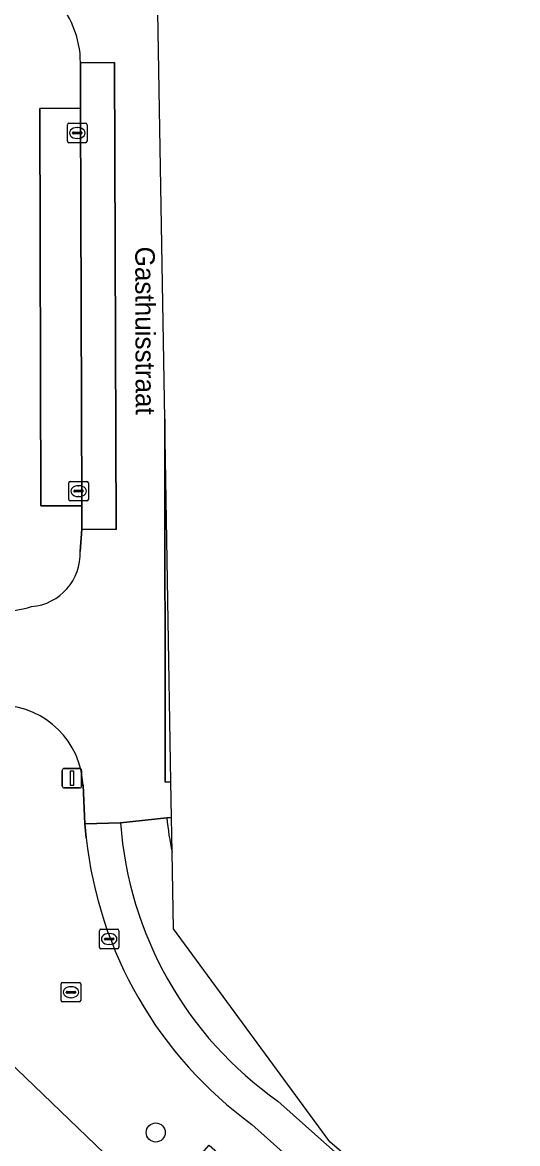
# Model space of a CAD drawing. Extents: x 161881 to 162523, y 381678 to 382381.
# Drawn here: x 162085.9 to 162111.3, y 382190.1 to 382247.6 of the extents above; entities that cross this region are included whole.
import ezdxf

# ---------------------------------------------------------------- set-up
doc = ezdxf.new("R2010")
doc.units = 0
for name, color, linetype in [('IMGEO_Boom', 7, 'Continuous'), ('IMGEO_Brandkraan', 7, 'Continuous'), ('IMGEO_Kolk', 7, 'Continuous'), ('IMGEO_Lichtmast', 7, 'Continuous'), ('IMGEO_Openbare_ruimte_label', 7, 'Continuous'), ('IMGEO_Pand', 7, 'Continuous'), ('IMGEO_Parkeervlak_open', 7, 'Continuous'), ('IMGEO_Rijbaan_lokaal_gesloten', 7, 'Continuous'), ('IMGEO_Rijbaan_lokaal_open', 7, 'Continuous'), ('IMGEO_Voetpad_open', 7, 'Continuous')]:
    doc.layers.add(name, color=color, linetype=linetype)

msp = doc.modelspace()

# ---------------------------------------------------------------- linework, layer by layer
at = {"layer": 'IMGEO_Boom'}
msp.add_circle((162092.765, 382190.639), 0.489, dxfattribs=at)
at = {"layer": 'IMGEO_Brandkraan'}
for p, q in [((162087.919, 382197.406), (162087.919, 382198.258)), ((162087.994, 382198.332), (162088.846, 382198.332)), ((162088.92, 382198.258), (162088.92, 382197.406)), ((162088.178, 382197.826), (162088.178, 382197.838)), ((162088.616, 382197.789), (162088.218, 382197.789)), ((162088.221, 382197.875), (162088.619, 382197.875)), ((162088.407, 382198.112), (162088.432, 382198.112)), ((162088.662, 382197.838), (162088.662, 382197.826)), ((162088.846, 382197.332), (162087.994, 382197.332)), ((162088.43, 382197.552), (162088.405, 382197.552))]:
    msp.add_line(p, q, dxfattribs=at)
for points in [[(162087.919, 382197.406), (162087.919, 382198.258)], [(162087.994, 382198.332), (162088.846, 382198.332)], [(162088.92, 382198.258), (162088.92, 382197.406)], [(162088.846, 382197.332), (162087.994, 382197.332)]]:
    msp.add_lwpolyline(points, dxfattribs=at)
for centre, radius, start, end in [((162087.996, 382198.256), 0.0765, 91.55205, 178.44795), ((162087.996, 382198.256), 0.0765, 91.55205, 178.44795), ((162088.844, 382198.256), 0.0765, 1.55205, 88.44795), ((162088.844, 382198.256), 0.0765, 1.55205, 88.44795), ((162088.218, 382197.835), 0.0403, 85.87752, 175.75265), ((162088.215, 382197.825), 0.0366, 178.93798, 274.71019), ((162088.619, 382197.832), 0.043, 264.86636, 352.45326), ((162088.623, 382197.837), 0.0386, 1.73085, 96.63898), ((162087.996, 382197.408), 0.0765, 181.55205, 268.44795), ((162087.996, 382197.408), 0.0765, 181.55205, 268.44795), ((162088.844, 382197.408), 0.0765, 271.55205, 358.44795), ((162088.844, 382197.408), 0.0765, 271.55205, 358.44795)]:
    msp.add_arc(centre, radius, start, end, dxfattribs=at)
for centre, major_axis, ratio, start_param, end_param in [((162088.406, 382197.832), (-0.387, 0.002), 0.722429, 4.712389, 7.853982), ((162088.431, 382197.832), (-0.39, 0.002), 0.717154, 1.570796, 4.712389)]:
    msp.add_ellipse(centre, major_axis=major_axis, ratio=ratio, start_param=start_param, end_param=end_param, dxfattribs=at)
at = {"layer": 'IMGEO_Kolk'}
for p, q in [((162088.243, 382241.473), (162088.243, 382242.325)), ((162088.318, 382242.399), (162089.17, 382242.399)), ((162088.502, 382241.893), (162088.502, 382241.905)), ((162088.545, 382241.942), (162088.943, 382241.942)), ((162088.731, 382242.179), (162088.756, 382242.179)), ((162088.986, 382241.905), (162088.986, 382241.893)), ((162089.244, 382242.325), (162089.244, 382241.473)), ((162089.17, 382241.399), (162088.318, 382241.399)), ((162088.94, 382241.856), (162088.542, 382241.856)), ((162088.754, 382241.619), (162088.729, 382241.619)), ((162088.31, 382223.104), (162088.31, 382223.956)), ((162088.385, 382224.03), (162089.237, 382224.03)), ((162088.569, 382223.524), (162088.569, 382223.536)), ((162089.007, 382223.487), (162088.609, 382223.487)), ((162088.612, 382223.573), (162089.01, 382223.573)), ((162088.798, 382223.81), (162088.823, 382223.81)), ((162089.053, 382223.536), (162089.053, 382223.524)), ((162089.311, 382223.956), (162089.311, 382223.104)), ((162089.237, 382223.03), (162088.385, 382223.03)), ((162088.821, 382223.25), (162088.796, 382223.25)), ((162089.952, 382201.062), (162090.804, 382201.062)), ((162089.877, 382200.136), (162089.877, 382200.988)), ((162090.136, 382200.556), (162090.136, 382200.568)), ((162090.574, 382200.519), (162090.176, 382200.519)), ((162090.179, 382200.605), (162090.577, 382200.605)), ((162090.365, 382200.842), (162090.39, 382200.842)), ((162090.62, 382200.568), (162090.62, 382200.556)), ((162090.878, 382200.988), (162090.878, 382200.136)), ((162090.804, 382200.062), (162089.952, 382200.062)), ((162090.388, 382200.282), (162090.363, 382200.282))]:
    msp.add_line(p, q, dxfattribs=at)
for points in [[(162088.243, 382241.473), (162088.243, 382242.325)], [(162088.318, 382242.399), (162089.17, 382242.399)], [(162089.244, 382242.325), (162089.244, 382241.473)], [(162089.17, 382241.399), (162088.318, 382241.399)], [(162088.31, 382223.104), (162088.31, 382223.956)], [(162088.385, 382224.03), (162089.237, 382224.03)], [(162089.311, 382223.956), (162089.311, 382223.104)], [(162089.237, 382223.03), (162088.385, 382223.03)], [(162089.952, 382201.062), (162090.804, 382201.062)], [(162089.877, 382200.136), (162089.877, 382200.988)], [(162090.878, 382200.988), (162090.878, 382200.136)], [(162090.804, 382200.062), (162089.952, 382200.062)]]:
    msp.add_lwpolyline(points, dxfattribs=at)
for centre, radius, start, end in [((162088.32, 382242.323), 0.0765, 91.55205, 178.44795), ((162088.32, 382242.323), 0.0765, 91.55205, 178.44795), ((162088.542, 382241.902), 0.0403, 85.87752, 175.75265), ((162088.539, 382241.892), 0.0366, 178.93798, 274.71019), ((162088.943, 382241.899), 0.043, 264.86636, 352.45326), ((162088.947, 382241.904), 0.0386, 1.73085, 96.63898), ((162089.168, 382242.323), 0.0765, 1.55205, 88.44795), ((162089.168, 382242.323), 0.0765, 1.55205, 88.44795), ((162088.32, 382241.475), 0.0765, 181.55205, 268.44795), ((162088.32, 382241.475), 0.0765, 181.55205, 268.44795), ((162089.168, 382241.475), 0.0765, 271.55205, 358.44795), ((162089.168, 382241.475), 0.0765, 271.55205, 358.44795), ((162088.387, 382223.954), 0.0765, 91.55205, 178.44795), ((162088.387, 382223.954), 0.0765, 91.55205, 178.44795), ((162088.609, 382223.533), 0.0403, 85.87752, 175.75265), ((162088.606, 382223.523), 0.0366, 178.93798, 274.71019), ((162089.01, 382223.53), 0.043, 264.86636, 352.45326), ((162089.014, 382223.535), 0.0386, 1.73085, 96.63898), ((162089.235, 382223.954), 0.0765, 1.55205, 88.44795), ((162089.235, 382223.954), 0.0765, 1.55205, 88.44795), ((162088.387, 382223.106), 0.0765, 181.55205, 268.44795), ((162088.387, 382223.106), 0.0765, 181.55205, 268.44795), ((162089.235, 382223.106), 0.0765, 271.55205, 358.44795), ((162089.235, 382223.106), 0.0765, 271.55205, 358.44795), ((162089.954, 382200.986), 0.0765, 91.55205, 178.44795), ((162089.954, 382200.986), 0.0765, 91.55205, 178.44795), ((162090.802, 382200.986), 0.0765, 1.55205, 88.44795), ((162090.802, 382200.986), 0.0765, 1.55205, 88.44795), ((162090.176, 382200.565), 0.0403, 85.87752, 175.75265), ((162090.173, 382200.555), 0.0366, 178.93798, 274.71019), ((162090.577, 382200.562), 0.043, 264.86636, 352.45326), ((162090.581, 382200.567), 0.0386, 1.73085, 96.63898), ((162089.954, 382200.138), 0.0765, 181.55205, 268.44795), ((162089.954, 382200.138), 0.0765, 181.55205, 268.44795), ((162090.802, 382200.138), 0.0765, 271.55205, 358.44795), ((162090.802, 382200.138), 0.0765, 271.55205, 358.44795)]:
    msp.add_arc(centre, radius, start, end, dxfattribs=at)
for centre, major_axis, ratio, start_param, end_param in [((162088.73, 382241.899), (-0.387, 0.002), 0.722429, 4.712389, 7.853982), ((162088.755, 382241.899), (-0.39, 0.002), 0.717154, 1.570796, 4.712389), ((162088.797, 382223.53), (-0.387, 0.002), 0.722429, 4.712389, 7.853982), ((162088.822, 382223.53), (-0.39, 0.002), 0.717154, 1.570796, 4.712389), ((162090.364, 382200.562), (-0.387, 0.002), 0.722429, 4.712389, 7.853982), ((162090.389, 382200.562), (-0.39, 0.002), 0.717154, 1.570796, 4.712389)]:
    msp.add_ellipse(centre, major_axis=major_axis, ratio=ratio, start_param=start_param, end_param=end_param, dxfattribs=at)
at = {"layer": 'IMGEO_Lichtmast'}
for p, q in [((162087.975, 382208.409), (162087.975, 382209.209)), ((162087.975, 382209.209), (162087.975, 382208.409)), ((162088.075, 382209.309), (162088.865, 382209.309)), ((162088.865, 382209.309), (162088.075, 382209.309)), ((162088.965, 382209.209), (162088.965, 382208.409)), ((162088.965, 382208.409), (162088.965, 382209.209)), ((162088.865, 382208.309), (162088.075, 382208.309)), ((162088.075, 382208.309), (162088.865, 382208.309))]:
    msp.add_line(p, q, dxfattribs=at)
msp.add_lwpolyline([(162088.395, 382209.184), (162088.545, 382209.184), (162088.545, 382208.434), (162088.395, 382208.434), (162088.395, 382209.184)], dxfattribs=at)
for centre, start, end in [((162088.075, 382209.209), 90, 180), ((162088.075, 382209.209), 90, 180), ((162088.865, 382209.209), 0, 90), ((162088.865, 382209.209), 360, 90), ((162088.075, 382208.409), 180, 270), ((162088.075, 382208.409), 180, 270), ((162088.865, 382208.409), 270, 0), ((162088.865, 382208.409), 270, 0)]:
    msp.add_arc(centre, 0.1, start, end, dxfattribs=at)
at = {"layer": 'IMGEO_Pand'}
msp.add_lwpolyline([(162067.56, 382193.772), (162067.774, 382193.996), (162067.692, 382194.083), (162071.649, 382198.284), (162073.593, 382196.41), (162078.546, 382196.531), (162078.626, 382194.019), (162074.741, 382193.897), (162075.168, 382179.155), (162081.552, 382179.326), (162084.022, 382177.24), (162082.333, 382175.326), (162082.586, 382175.12), (162085.015, 382177.926), (162087.132, 382180.372), (162087.289, 382180.239), (162092.935, 382186.87), (162092.832, 382186.958), (162085.181, 382194.323)], dxfattribs=at)
at = {"layer": 'IMGEO_Parkeervlak_open'}
msp.add_lwpolyline([(162088.916, 382243.166), (162086.821, 382243.155), (162086.88, 382222.774), (162088.977, 382222.779)], close=True, dxfattribs=at)
at = {"layer": 'IMGEO_Rijbaan_lokaal_gesloten'}
for points in [[(162088.975, 382221.581), (162090.73, 382221.57), (162090.649, 382245.517), (162088.905, 382245.498), (162088.916, 382243.166), (162088.977, 382222.779)], [(162093.544, 382208.615), (162093.226, 382227.227), (162093.226, 382227.208), (162093.251, 382208.601), (162093.544, 382208.615)]]:
    msp.add_lwpolyline(points, close=True, dxfattribs=at)
for points in [[(162090.961, 382206.52), (162089.135, 382206.465), (162089.203, 382205.753)], [(162093.606, 382205.009), (162093.575, 382206.795), (162093.575, 382206.795), (162093.327, 382206.78)], [(162101.232, 382190.273), (162099.021, 382192.248)], [(162097.689, 382191.053), (162100.103, 382188.901), (162107.147, 382182.753), (162108.526, 382181.527), (162109.659, 382182.83), (162101.232, 382190.273)]]:
    msp.add_lwpolyline(points, dxfattribs=at)
for centre, radius, start, end in [((162110.074, 382207.902), 19.163, 184.13607, 234.77443), ((162111.15, 382208.68), 17.924, 186.08571, 191.81777), ((162110.074, 382208.002), 20.992, 186.15007, 233.84379)]:
    msp.add_arc(centre, radius, start, end, dxfattribs=at)
at = {"layer": 'IMGEO_Rijbaan_lokaal_open'}
for points in [[(162089.043, 382208.449), (162089.135, 382206.465), (162090.961, 382206.52), (162093.327, 382206.78), (162093.575, 382206.795), (162093.575, 382206.795), (162093.544, 382208.615), (162093.544, 382208.615), (162093.251, 382208.601), (162093.226, 382227.208), (162093.226, 382227.227), (162092.784, 382253.072), (162092.582, 382264.872)], [(162088.905, 382245.498), (162090.649, 382245.517), (162090.73, 382221.57), (162088.975, 382221.581), (162088.887, 382220.442)], [(162093.327, 382206.78), (162090.961, 382206.52)], [(162109.883, 382183.088), (162101.683, 382190.161), (162093.673, 382201.086), (162093.606, 382205.009)], [(162099.021, 382192.248), (162101.232, 382190.273), (162109.659, 382182.83), (162109.883, 382183.088)]]:
    msp.add_lwpolyline(points, dxfattribs=at)
for centre, radius, start, end in [((162084.168, 382245.525), 4.737, 359.67492, 91.36213), ((162086.181, 382220.312), 2.709, 274.66311, 2.74182), ((162084.331, 382224.582), 7.271, 272.67312, 286.54125), ((162084.723, 382208.231), 4.325, 2.88969, 87.47224), ((162110.074, 382207.902), 19.163, 184.13607, 234.77443), ((162111.15, 382208.68), 17.924, 186.08571, 191.81777)]:
    msp.add_arc(centre, radius, start, end, dxfattribs=at)
at = {"layer": 'IMGEO_Voetpad_open'}
for points in [[(162088.887, 382220.442), (162088.975, 382221.581), (162088.977, 382222.779), (162086.88, 382222.774), (162086.821, 382243.155), (162088.916, 382243.166), (162088.905, 382245.498)], [(162084.914, 382212.552), (162084.606, 382210.465), (162084.988, 382198.879), (162083.795, 382198.85), (162083.88, 382196.772), (162085.053, 382196.837), (162085.181, 382194.323), (162092.832, 382186.958), (162095.504, 382189.989), (162101.353, 382184.848), (162107.416, 382179.84), (162107.127, 382179.509), (162109.213, 382177.62), (162111.309, 382175.703)], [(162089.203, 382205.753), (162089.135, 382206.465), (162089.043, 382208.449)], [(162109.411, 382180.74), (162108.526, 382181.527), (162107.147, 382182.753), (162100.103, 382188.901), (162097.689, 382191.053)]]:
    msp.add_lwpolyline(points, dxfattribs=at)
for centre, radius, start, end in [((162084.168, 382245.525), 4.737, 359.67492, 91.36213), ((162086.181, 382220.312), 2.709, 274.66311, 2.74182), ((162084.331, 382224.582), 7.271, 272.67312, 286.54125), ((162084.723, 382208.231), 4.325, 2.88969, 87.47224), ((162110.074, 382208.002), 20.992, 186.15007, 233.84379)]:
    msp.add_arc(centre, radius, start, end, dxfattribs=at)

# ---------------------------------------------------------------- texts
at = {"layer": 'IMGEO_Openbare_ruimte_label'}
msp.add_text('Gasthuisstraat', height=1, rotation=270.17189, dxfattribs=at).set_placement((162091.714, 382236.07))

doc.saveas('drawing.dxf')
